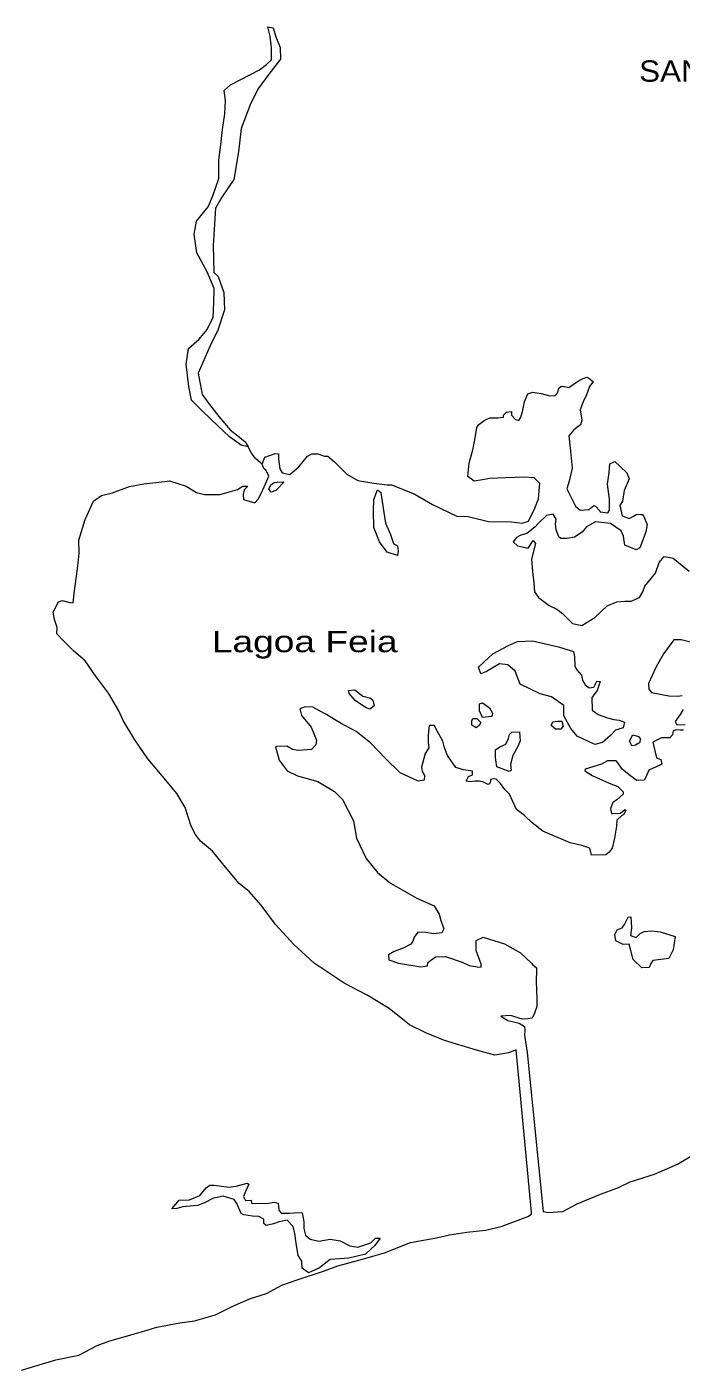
# Model space of a CAD drawing. Extents: x 47169 to 972804, y 7447977 to 9608469.
# Drawn here: x 248175 to 267595, y 7542631 to 7582474 of the extents above; entities that cross this region are included whole.
import ezdxf

# ---------------------------------------------------------------- set-up
doc = ezdxf.new("R2010")
doc.units = 0
doc.header["$LTSCALE"] = 270
doc.layers.add('1', color=7, linetype='Continuous', lineweight=13)
doc.layers.add('3', color=7, linetype='Continuous')

msp = doc.modelspace()

# ---------------------------------------------------------------- linework, layer by layer
at = {"layer": '1'}
for points in [[(255158.8, 7569499.2), (254959.7, 7569673.4), (254843.7, 7569826.6), (254747.8, 7570013.5), (254540.2, 7570065.7), (254185, 7570314.9), (253838.9, 7570641.9), (253398.1, 7571067.1), (253062.1, 7571405.3), (252983.6, 7571802.9), (252900.9, 7572466.3), (252976.3, 7572932.8), (253292.4, 7573214.7), (253525.7, 7573495.3), (253706.1, 7573863.7), (253720.2, 7574284.8), (253734.1, 7574717.1), (253530, 7575212.5), (253221.5, 7575772.7), (253140.5, 7576325.3), (253206.9, 7576714.1), (253551.8, 7577140.4), (253691.5, 7577463.9), (253869.7, 7577976.2), (253871.6, 7578519.1), (253936.9, 7578974.3), (253981.6, 7579429.2), (254046.7, 7579895.5), (254071.6, 7580294.7), (254036.1, 7580582.2), (254219.6, 7580751.2), (254814.7, 7581059.5), (255081.5, 7581196.6), (255285.9, 7581354.8), (255438.7, 7581501.2), (255433.3, 7581855.6), (255397, 7582198.5), (255353.2, 7582352.9), (255330.7, 7582474.4), (255486.3, 7582443.5), (255562.8, 7582178.8), (255691.8, 7581859.6), (255707.4, 7581516.4), (255352.3, 7581067.8), (255028.1, 7580630.8), (254807.9, 7580162.1), (254539.5, 7579460), (254457.1, 7578771.9), (254314.7, 7577949.9), (253961, 7577423.7), (253769.5, 7577099.5), (253704, 7575990.7), (253726.8, 7575193.4), (253852.7, 7575073.5), (254025.4, 7574599.8), (254043.9, 7574079.4), (253846.4, 7573478.1), (253605.8, 7572998), (253256.4, 7572206), (253380.1, 7571565.4), (253591.4, 7571269.5), (253875.9, 7570919.5), (254212.7, 7570525.9), (254484.8, 7570308.5), (254652.4, 7570167.1), (254747.8, 7570013.5)], [(260219.9, 7568302.8), (260938.1, 7567959.2), (261268.8, 7567953.1), (261351.8, 7567932.2), (261880.6, 7567807.2), (262562.8, 7567795.3), (262873.3, 7567755.7), (263068.8, 7567814), (263249.1, 7568193.4), (263358.5, 7568471.9), (263385.9, 7568716.1), (263403.4, 7568926.8), (263235.5, 7569101.5), (262945.9, 7569119.3), (262388.2, 7569099.9), (261913.1, 7569081.7), (261696.8, 7569034.1), (261449.4, 7568997.1), (261261.2, 7569138.3), (261306.9, 7569537.8), (261414.7, 7569927.1), (261472.1, 7570227.1), (261528.6, 7570593.5), (261589.3, 7570683.1), (261752.9, 7570796.3), (261917.1, 7570876.3), (262165.1, 7570880), (262319.9, 7570893.5), (262318.9, 7570959.9), (262410.5, 7571049.9), (262555, 7571063.2), (262556.7, 7570952.4), (262682.5, 7570832.4), (262776, 7570800.6), (262826.5, 7570878.9), (262885.8, 7571057), (262943.3, 7571357), (263013.2, 7571524.2), (263043.2, 7571591.1), (263197.5, 7571637.7), (263435.8, 7571597), (263695.1, 7571534.4), (263860.4, 7571536.9), (263931.4, 7571626.5), (263960.5, 7571759.9), (264032, 7571816.4), (264135.5, 7571806.8), (264259.9, 7571775.5), (264546.3, 7571979.1), (264690, 7572047.7), (264792.8, 7572082.5), (264855.3, 7572050.2), (264980.8, 7571952.3), (264879.6, 7571806.8), (264790.2, 7571561.8), (264690, 7571349.8), (264600.5, 7571115.9), (264646.4, 7570806.4), (264607.1, 7570672.9), (264412.9, 7570526), (264260.6, 7570346.5), (264297, 7569981.4), (264357.6, 7569384.2), (264270.4, 7568995.1), (264201.4, 7568772.6), (264457, 7568255.7), (264593.2, 7568135.9), (264851.1, 7568161.9), (265004.4, 7568275), (265056.4, 7568253.6), (265182.3, 7568122.5), (265193.1, 7568089.4), (265420.9, 7568059.6), (265471.4, 7568137.9), (265466.5, 7568470.1), (265408.2, 7568912.4), (265454.8, 7569256.5), (265482, 7569511.7), (265625.7, 7569580.2), (265782.8, 7569438.6), (265982, 7569242.1), (266057, 7569066), (265996.9, 7568932.2), (265907.1, 7568720.4), (265849.7, 7568409.4), (265779.3, 7568275.4), (265845.9, 7567966.2), (266053.7, 7567891.7), (266176.6, 7567960), (266279.1, 7568016.9), (266403.2, 7568007.7), (266444.6, 7568008.3), (266476, 7567975.5), (266583.3, 7567711.2), (266545.1, 7567500.2), (266465.7, 7567277.5), (266366.2, 7567021.2), (266263.7, 7566964.3), (265920.7, 7567103.2), (265885.8, 7567368.6), (265811.2, 7567522.6)], [(261229.7, 7546727.1), (261786.1, 7546779.9), (262248.8, 7546886.6), (263049.1, 7547186.8), (263151.3, 7547254.8), (263150.3, 7547321.3), (262695.6, 7552133.3), (262469.9, 7552041.2), (262068.5, 7551968.7), (261519, 7552126.5), (260575.3, 7552411.3), (260014.5, 7552635.3), (259536, 7552871.7), (258929.7, 7553360.9), (258273.4, 7553749.7), (257596.9, 7554104.8), (256699.8, 7554700.3), (256092.1, 7555266.9), (255556.6, 7555845.7), (255134.5, 7556426.3), (254777.1, 7556830.7), (254474, 7557069.7), (254074.1, 7557550.9), (253684.6, 7558021.2), (253328.7, 7558325.8), (253181, 7558522.9), (253053.3, 7558764.6), (252869.1, 7559315.6), (252625, 7559732.8), (252298.6, 7560126.5), (251761.9, 7560760.6), (251381.1, 7561330.7), (251031.2, 7561901.2), (250902.7, 7562187.3), (250594.8, 7562714.2), (250214.8, 7563228.9), (249908.2, 7563667.1), (249573, 7563961), (249279.2, 7564244.3), (249068.9, 7564473.7), (249076.3, 7564662.1), (249000.3, 7564893.6), (248955.4, 7565114.4), (249116, 7565416.1), (249228.9, 7565462.2), (249446.8, 7565399.2), (249550.3, 7565389.8), (249586, 7565744.9), (249669.7, 7566333.4), (249697, 7566566.4), (249723.2, 7566866), (249717.1, 7567253.6), (249903.7, 7567865.9), (250153.6, 7568401.7), (250388.6, 7568571.5), (250718, 7568654.3), (251221.4, 7568839.5), (251643.8, 7568923.7), (252273.1, 7568988.9), (252407.1, 7569013.2), (252905.6, 7568854.8), (253208.3, 7568660.1), (253446.8, 7568608.5), (253901.6, 7568604.5), (254076.5, 7568651.5), (254426.2, 7568756.7), (254590.1, 7568847.8), (254734.8, 7568850.1), (254622.9, 7568737.5), (254593.9, 7568604.2), (254606.5, 7568460.3), (254938.8, 7568354.7), (255040.4, 7568467.1), (255130.8, 7568634.6), (255220.7, 7568835.4), (255300.6, 7569013.9), (255360.5, 7569147.8), (255275.3, 7569312.7), (255212.3, 7569378.2), (255158.8, 7569499.2), (255238.1, 7569710.9), (255546.6, 7569815.4), (255639.7, 7569805.7), (255642, 7569661.8), (255687.9, 7569363.4), (255751.8, 7569242.5), (255979.8, 7569201.7), (256245, 7569427.3), (256508.8, 7569741.6), (256631.8, 7569810), (256807.4, 7569812.7), (257004.9, 7569738.1), (257108.2, 7569739.7), (257307.1, 7569576.6), (257674.4, 7569205.6), (257997.6, 7569022.2), (258474.2, 7568940.9), (258867.6, 7568891.5), (259001.9, 7568893.5), (259667.3, 7568626.7), (260219.9, 7568302.8)], [(265811.2, 7567522.6), (265498, 7567739.5), (265053, 7567788.3), (264786.5, 7567640.3), (264654.5, 7567483.2), (264429.4, 7567335.9), (264202.7, 7567299.2), (264027.1, 7567296.6), (263964.3, 7567351.1), (263888.8, 7567560.4), (263865.5, 7567737.3), (263884.2, 7567870.5), (263799.2, 7568024.4), (263603.6, 7567977.1), (263369.2, 7567763.1), (263257.4, 7567639.6), (263012.3, 7567447.6), (262837.3, 7567400.7), (262704, 7567332.2), (262613.1, 7567197.9), (262738.8, 7567077.9), (263049.7, 7567016.1), (263201.4, 7567240), (263275, 7567152.4), (263158, 7566685.4), (263184.2, 7566320.2), (263220.3, 7565977.4), (263244.9, 7565711.9), (263361, 7565547.5), (263601.2, 7565373.8), (263674.5, 7565308.5), (263903.4, 7565201.1), (264070.7, 7565070.7), (264374.7, 7564776.1), (264644.2, 7564713.7), (265033.2, 7564952.1), (265399.9, 7565301), (265687.4, 7565416), (265924.7, 7565441.7), (266110.6, 7565444.4), (266357, 7565547.8), (266457.8, 7565715.4), (266517.3, 7565882.5), (266831.8, 7566274.9), (266940.8, 7566586.6), (267093.2, 7566766.1), (267362.5, 7566714.7), (267833, 7566333.9)], [(268372.2, 7564093.1), (267594.5, 7564292.2), (267377.6, 7564289), (267073.8, 7563874.6), (266842.2, 7563472.4), (266622.1, 7562992.8), (266634.8, 7562826.9), (266718.9, 7562728.4), (267226.4, 7562636.2), (267484.9, 7562617.9), (267629.1, 7562642.1)], [(265561.2, 7560706.2), (265406.3, 7560703.9), (265232.3, 7560601.6), (264749, 7560461.4), (264739.5, 7560405.9), (264958.5, 7560265.2), (265457.5, 7560040), (265717.1, 7559944.1), (265874.5, 7559780.3), (265875.5, 7559713.9), (265681.8, 7559544.8), (265569.3, 7559465.6), (265499.7, 7559287.3), (265532.8, 7559143.8), (265574.1, 7559144.4), (265790.9, 7559147.7), (265923.5, 7559260.4), (265954.8, 7559238.7), (265894.7, 7559116), (265823.1, 7559070.6), (265690.7, 7558946.8), (265672.7, 7558769.2), (265616, 7558413.9), (265548.2, 7558113.8), (265457.1, 7557990.6), (265355, 7557911.5), (264931.7, 7557905.2), (264887.3, 7558115), (264648.7, 7558189), (264296.4, 7558272.4), (263485.8, 7558614.7), (263172.2, 7558864.8), (262941.8, 7559082.8), (262711.9, 7559256.6), (262498.4, 7559718.7), (262362.2, 7559849.5), (262235.5, 7560036), (262109.7, 7560155.9), (262027, 7560165.7), (261934.2, 7560153.3), (261935.2, 7560086.8), (261905.2, 7560019.9), (261864.2, 7559997.1), (261728.9, 7560072.6), (261614.8, 7560104.1), (261480.6, 7560102.1), (261315.7, 7560077.4), (261212.1, 7560098), (261282.2, 7560243.1), (261405.4, 7560289.3), (261403.7, 7560400), (261134.6, 7560440.2), (260906.5, 7560503.2), (260663.4, 7560865.1), (260567.1, 7561085.2), (260522.8, 7561284), (260331.7, 7561624.5), (260278, 7561756.6), (260112.8, 7561754.1), (260086.2, 7561465.7), (260089.4, 7561255.2), (260102.3, 7561089.2), (260001.6, 7560921.5), (259883.7, 7560520.9), (259906.4, 7560388.4), (259980.5, 7560267.6), (259972.2, 7560134.5), (259786.9, 7560098.5), (259256.4, 7560345.2), (258816.1, 7560770.5), (258375.1, 7561240.1), (257946.5, 7561576.9), (257509, 7561813.9), (257029.6, 7562094.6), (256862.8, 7562191.7), (256664.9, 7562299.4), (256437.5, 7562307), (256273.1, 7562249.1), (256327.8, 7562050.5), (256612.1, 7561700.4), (256773, 7561315.2), (256754.4, 7561181.9), (256622.4, 7561035.9), (256230.4, 7561007.6), (256064.6, 7561038.3), (255887.5, 7561135.3), (255598.4, 7561130.8), (255557.3, 7561119.1), (255666.7, 7560722), (255898.9, 7560404.3), (256211, 7560254), (256812.7, 7560086.1), (257302.6, 7559794.5), (257543.8, 7559554.5), (257873.6, 7558928.1), (257964.2, 7558408.9), (258242, 7557803.8), (258578.8, 7557388), (258965.7, 7557072.7), (259746.9, 7556630.5), (260266.6, 7556405.7)], [(267656, 7562221.6), (267565.2, 7562076.2), (267413.2, 7561874.6), (267466.3, 7561775.7), (267714.2, 7561779.4)], [(267665, 7561612.5), (267572, 7561611.1), (267448, 7561620.4), (267355.4, 7561596.8), (267336.5, 7561474.7), (267255.2, 7561384.9), (267121, 7561382.9), (267007.4, 7561381.2), (266751.1, 7561255.6), (266861.2, 7560791.9), (266996.2, 7560738.5), (267018.9, 7560606), (266834.3, 7560514.6), (266639.5, 7560423.1), (266539.5, 7560200.1), (266499.2, 7560133), (266282.5, 7560118.7), (266105, 7560249), (265843.8, 7560455.6), (265727.6, 7560631.1), (265664.5, 7560707.7), (265561.2, 7560706.2)], [(260266.6, 7556405.7), (260415, 7556153.2), (260459.1, 7555965.6), (260555.8, 7555723.3), (260495.7, 7555600.5), (260248.3, 7555574.6), (260020.5, 7555615.4), (259783, 7555622.9), (259671.6, 7555477.2), (259632.2, 7555354.7), (259571.6, 7555265.2), (259346.2, 7555150.9), (259079.4, 7555047.1), (258905.4, 7554944.8), (258918, 7554800.9), (259208.5, 7554705.7), (259871, 7554594), (260066.7, 7554619.1), (260075.5, 7554719), (260300.1, 7554888.5), (260599.2, 7554904.2), (261097.4, 7554734.5), (261305.3, 7554638), (261543.4, 7554597.3), (261657.1, 7554587.9), (261655.7, 7554676.5), (261515.5, 7555073.2), (261511, 7555372.3), (261715.9, 7555475.1), (262348.7, 7555274.2), (262827.7, 7555004.5), (263152.4, 7554699.2), (263194.3, 7554655.5), (263298.9, 7554568.5), (263300.7, 7554446.6), (263293.9, 7554213.9), (263299.6, 7553837.3), (263312.1, 7553693.5), (263316.2, 7553416.6), (263247, 7553216.2), (263176.9, 7553071.1), (263053.4, 7553047.1), (262888.3, 7553044.6), (262525.4, 7553149.9), (262246.9, 7553134.6), (262455.3, 7553004.8), (262786.9, 7552921.2), (262943.2, 7552823.9), (262955.4, 7552702.2), (262947.1, 7552569.1), (263027.2, 7552049.7), (263500.9, 7547337.6), (263645.8, 7547306.6), (264078.8, 7547335.3), (264508.7, 7547563.3), (265154.9, 7547827.8), (265739.8, 7548047.1), (266077.8, 7548218.3), (266807.2, 7548439.6), (267483.8, 7548737.7), (268005.6, 7549044.5)], [(248014.7, 7542631.1), (249031.2, 7542935.5), (249720.1, 7543079.5), (250262.4, 7543365.2), (250611.2, 7543492.6), (251258.2, 7543680.2), (251679.3, 7543797.7), (252028.5, 7543902.9), (252717.6, 7544035.7), (253150, 7544097.9), (253776.6, 7544274), (254288.6, 7544525.8), (254811.2, 7544755.6), (255283.4, 7544907), (255744, 7545146.8), (256195.5, 7545309), (256975.7, 7545564.9), (257406.5, 7545726.6), (258033.4, 7545891.5), (258793.5, 7546113.7), (259562.8, 7546413.5), (260334.5, 7546558.3), (260715, 7546641.7), (261229.7, 7546727.1)]]:
    msp.add_lwpolyline(points, dxfattribs=at)
for points in [[(255600.9, 7568974.3), (255797.2, 7568977.3), (255756.7, 7568921.3), (255665.3, 7568820.2), (255563.5, 7568718.9), (255429.9, 7568672.5), (255356.2, 7568760), (255416.1, 7568893.9), (255518.4, 7568961.9)], [(259059.4, 7567155.2), (259174.2, 7567079.4), (259197.3, 7566924.6), (259178.6, 7566791.4), (258867.1, 7566897.5), (258645.4, 7567204.2), (258473.7, 7567622.6), (258466.2, 7568109.9), (258471.3, 7568453.4), (258580.5, 7568743.1), (258685, 7568667.2), (258754.1, 7568202.9), (258823, 7567749.8), (258972.7, 7567419.7)], [(265037.7, 7561185.8), (264507.2, 7561432.7), (264317.9, 7561662.5), (264116.1, 7562036.1), (264111.4, 7562346.2), (263746, 7562606.6), (263414.2, 7562690.2), (262821.1, 7562980.4), (262670.7, 7563365.9), (262451, 7563550.9), (262202.6, 7563580.4), (261813.5, 7563352.9), (261649.3, 7563284), (261584.3, 7563482.4), (261747.2, 7563640), (262001.9, 7563876.4), (262473.3, 7564127.3), (262740.2, 7564242.1), (263184.1, 7564259.8), (263951.2, 7564083), (264397.4, 7563945.6), (264430.5, 7563802.1), (264434.8, 7563514.2), (264498.5, 7563404.3), (264635.2, 7563240.2), (264668.3, 7563096.7), (264742.7, 7562953.8), (264868, 7562867), (265001.9, 7562891.2), (265092.2, 7563069.8), (265195.6, 7563060.3), (265106.7, 7562793.1), (264944.6, 7562580.2), (264950.2, 7562203.6), (265127.7, 7562073.3), (265408, 7561977.8), (265594.7, 7561925.2), (265760.2, 7561905.5), (265916, 7561852.4), (265877.1, 7561685.7), (265651, 7561615.9), (265498.4, 7561458.5), (265264, 7561244.5)], [(257922, 7562496), (257743.2, 7562703.8), (257721.2, 7562792.1), (257906.9, 7562806), (258147.4, 7562621.4), (258375.6, 7562558.4), (258448.7, 7562504.1), (258482.2, 7562338.5), (258359.8, 7562236.9), (258224.7, 7562290.2)], [(261902.1, 7562279.7), (261997.5, 7562115), (261978.4, 7562015), (261699.9, 7561988.6), (261614.2, 7562186.8), (261611.1, 7562397.2), (261703.7, 7562420.7)], [(261650.4, 7561843.9), (261600.1, 7561754.5), (261508.2, 7561686.6), (261383.1, 7561762.3), (261381.1, 7561895.2), (261411.1, 7561962.1), (261535, 7561964)], [(263863.7, 7561644.6), (263738.2, 7561753.5), (263788.1, 7561865), (263922.2, 7561878.1), (264056.4, 7561880.1), (264089.6, 7561736.6), (264028.9, 7561647)], [(262815.5, 7561296.5), (262755.7, 7561151.6), (262594.8, 7560861.1), (262526.4, 7560605.3), (262549.8, 7560417.4), (262488.4, 7560383.2), (262124.8, 7560521.7), (262089.7, 7560798.1), (262086.2, 7561030.7), (262208.7, 7561121.2), (262393.4, 7561201.5), (262473.5, 7561368.9), (262502.8, 7561480.1), (262574, 7561558.7), (262801.1, 7561562.1), (262803.3, 7561418.2)], [(266133, 7561146.7), (266058.6, 7561289.6), (266159, 7561479.4), (266325.1, 7561426.5), (266388.2, 7561349.9), (266358.8, 7561238.7), (266235.9, 7561170.4)], [(266968.6, 7555631.4), (267414.6, 7555494), (267358.6, 7555094.4), (267228.2, 7554837.7), (266836.6, 7554787.5), (266754.1, 7554786.3), (266693.5, 7554696.8), (266643.7, 7554574.2), (266427.1, 7554559.9), (266175.6, 7554811), (266088.4, 7555119.8), (266055.3, 7555263.3), (265869.5, 7555260.6), (265661.4, 7555368.2), (265627.6, 7555556.1), (265697.9, 7555690), (265841.6, 7555747.6), (265912.3, 7555848.3), (266022.6, 7556071.5), (266105.2, 7556072.8), (266120.3, 7555751.7), (266092.8, 7555518.7), (266258.7, 7555465.8), (266381, 7555578.4), (266493.5, 7555646.5), (266720.4, 7555661)], [(256860.6, 7545662.8), (256624.9, 7545559.4), (256532.8, 7545513.7), (256344.9, 7545654.8), (256341.6, 7545865.2), (256225.5, 7546029.6), (256168.2, 7546394.3), (256132.8, 7546681.7), (256077.9, 7546891.4), (255899.6, 7547076.9), (255663, 7547028.9), (255498.8, 7546971), (255282.8, 7546923.3), (255209.8, 7546977.5), (255207.7, 7547110.5), (255062, 7547185.7), (254876.1, 7547193.9), (254617.5, 7547234.2), (254534.3, 7547277.2), (254405.8, 7547574.3), (254331.7, 7547695), (253999.9, 7547789.5), (253773.6, 7547741.6), (253711.9, 7547729.5), (253445.8, 7547592.4), (253240.6, 7547511.6), (252807.8, 7547471.6), (252622.8, 7547424.3), (252478.5, 7547411), (252691.2, 7547669.1), (253000.5, 7547685.1), (253308.1, 7547811.8), (253500.7, 7548036.4), (253602.6, 7548115.6), (253736.8, 7548117.7), (254171.2, 7548058), (254387.5, 7548083.6), (254716.3, 7548177.4), (254768.4, 7548145), (254668.5, 7547932.9), (254609, 7547776.9), (254662.3, 7547666.9), (254837.7, 7547669.7), (254839.1, 7547581.1), (255293.2, 7547577.1), (255519.7, 7547613.9), (255633.7, 7547582.4), (255657.6, 7547372.3), (255720.9, 7547284.6), (255968.5, 7547288.5), (256205.7, 7547303.3), (256350.3, 7547294.5), (256395.7, 7547029.3), (256398.8, 7546829.9), (256443.1, 7546631.2), (256579.2, 7546511.5), (256837.9, 7546460.1), (257177.5, 7546520.7), (257477.6, 7546470), (257758.5, 7546319.2), (257996.5, 7546278.6), (258386.6, 7546406.5), (258518.7, 7546541.5), (258663.1, 7546543.7), (258501.3, 7546330.7), (258389.5, 7546218.2), (258226.7, 7546071.7), (257733.2, 7545953.3), (257176.7, 7545911.4)]]:
    msp.add_lwpolyline(points, close=True, dxfattribs=at)

# ---------------------------------------------------------------- texts
at = {"layer": '3'}
for s, height, width, p in [('SANTO SEBASTIÃO DE CAMPOS', 634.6, 1.1, (266347.4, 7580846.5)), ('Lagoa Feia', 634, 1.3, (253664.6, 7563925.7))]:
    msp.add_text(s, height=height, dxfattribs=dict(at, width=width)).set_placement(p)

doc.saveas('drawing.dxf')
